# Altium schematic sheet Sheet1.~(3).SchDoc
size A4
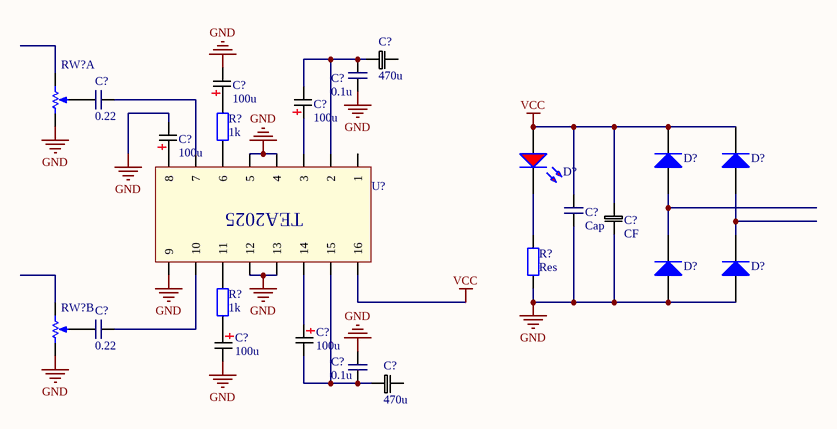
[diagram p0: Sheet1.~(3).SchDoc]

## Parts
(Parts that share a designator on the sheet are numbered #1, #2 ... from top to bottom, then left to right.)
C?#1  470u  [CF0.1]
C?#2  0.1u  [RAD0.1]
C?#3  100u  [CF0.1]
C?#4  0.22  [RAD0.1]
C?#5  100u  [CF0.1]
C?#6  100u  [CF0.1]
C?#7  Cap  [RAD0.1]
C?#8  CF  [CF0.1]
C?#9  0.22  [RAD0.1]
C?#10  100u  [CF0.1]
C?#11  100u  [CF0.1]
C?#12  0.1u  [RAD0.1]
C?#13  470u  [CF0.1]
D?#1  LED0  [LED]  (value not drawn)
D?#2  Diode 1N4007  [DIO10.46-5.3x2.8]  (value not drawn)
D?#3  Diode 1N4007  [DIO10.46-5.3x2.8]  (value not drawn)
D?#4  Diode 1N4007  [DIO10.46-5.3x2.8]  (value not drawn)
D?#5  Diode 1N4007  [DIO10.46-5.3x2.8]  (value not drawn)
R?#1  1k  [AXIAL-0.3]
R?#2  Res  [AXIAL-0.3]
R?#3  1k  [AXIAL-0.3]
RW?#1  RW  [RW]  (value not drawn)  (part A of 2)
RW?#2  RW  [RW]  (value not drawn)  (part B of 2)
U?  TEA2025  [DIP16]  (value not drawn)

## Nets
GND: C?#2.1 C?#3.2 C?#6.2 C?#7.1 C?#8.2 C?#11.2 C?#12.2 D?#4.1(A) D?#5.1(A) R?#2.1 RW?#1.1(TOP) RW?#2.4(TOP) U?.4 U?.5 U?.9 U?.12 U?.13
VCC: C?#7.2 C?#8.1 D?#1.1(A) D?#2.2(K) D?#3.2(K) U?.16
NetC?#1_1: C?#1.1 C?#2.2 C?#5.2 U?.2
NetC?#3_1: C?#3.1 R?#1.2
NetC?#4_1: C?#4.1 RW?#1.2(TAP)
NetC?#4_2: C?#4.2 U?.7
NetC?#5_1: C?#5.1 U?.3
NetC?#6_1: C?#6.1 U?.8
NetC?#9_1: C?#9.1 RW?#2.5(TAP)
NetC?#9_2: C?#9.2 U?.10
NetC?#10_1: C?#10.1 U?.14
NetC?#10_2: C?#10.2 C?#12.1 C?#13.1 U?.15
NetC?#11_1: C?#11.1 R?#3.1
NetD?#1_2: D?#1.2(K) R?#2.2
NetD?#2_1: D?#2.1(A) D?#4.2(K)
NetD?#3_1: D?#3.1(A) D?#5.2(K)
NetR?#1_1: R?#1.1 U?.6
NetR?#3_2: R?#3.2 U?.11

Not connected (* = marked no-connect by the designer): C?#1 2; C?#13 2; RW?#1 3(BOT); RW?#2 6(BOT); U? 1

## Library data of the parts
C?#1 C?#13 = CF
C?#2 C?#4 C?#9 C?#12 = Cap
C?#3 C?#5 C?#6 C?#10 C?#11 = Cap Pol
D?#2-D?#5 = Diode 1N4007: 1 Amp General Purpose Rectifier
R?#1 R?#3 = Res: Resistor
R?#2 = Res: Resistor; Value: 1K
